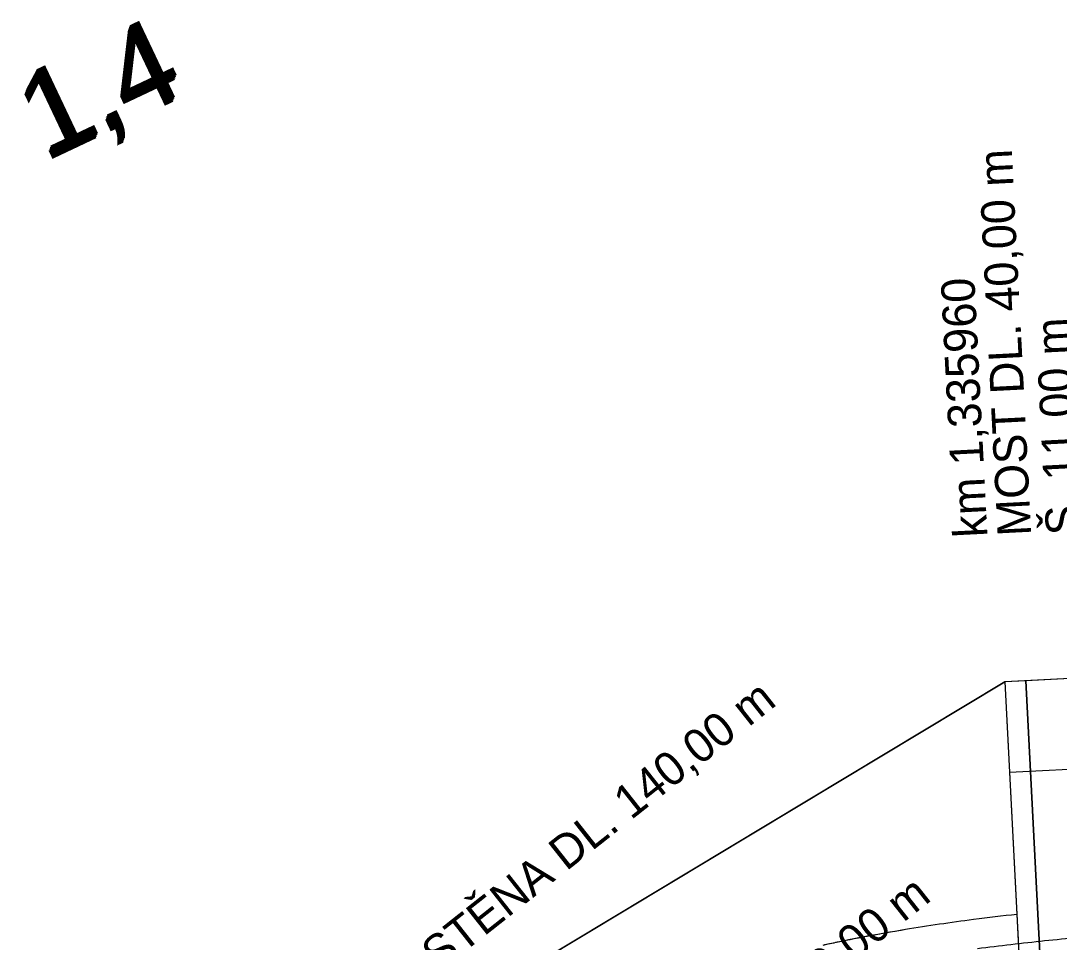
# Model space of a CAD drawing. Extents: x -606444 to -604546, y -1158114 to -1156869.
# Drawn here: x -606155.8 to -606032.4, y -1157301.1 to -1157191.5 of the extents above; entities that cross this region are included whole.
import ezdxf

# ---------------------------------------------------------------- set-up
doc = ezdxf.new("R2010")
doc.units = 0
for name, color, linetype in [('B_CHOD', 7, 'Continuous'), ('B_TRAM', 7, 'Continuous'), ('B_VOZ', 7, 'Continuous'), ('B_ZELEN', 7, 'Continuous'), ('NS_VB', 7, 'Continuous'), ('NS_VB_OBJ', 7, 'Continuous'), ('NS_VB_POP', 7, 'Continuous'), ('OSA', 7, 'Continuous'), ('OSAPOP', 7, 'Continuous')]:
    doc.layers.add(name, color=color, linetype=linetype)

msp = doc.modelspace()

# ---------------------------------------------------------------- linework, layer by layer
at = {"layer": 'B_CHOD'}
for p, q in [((-606036.36, -1157270), (-606038.86, -1157270.13)), ((-606038.86, -1157270.13), (-606035.78, -1157330.33)), ((-606033.28, -1157330.2), (-606036.36, -1157270))]:
    msp.add_line(p, q, dxfattribs=at)
msp.add_lwpolyline([(-606036.36, -1157270), (-606036.36, -1157270)], dxfattribs=at)
at = {"layer": 'B_TRAM'}
msp.add_lwpolyline([(-606037.44, -1157297.79), (-606036.88, -1157308.8)], dxfattribs=at)
for centre, radius, start, end in [((-606011.41, -1157540.2), 243.79, 97.3485, 99.2721), ((-605999.21, -1157634.73), 339.1, 96.473, 97.3485), ((-606019.94, -1157487.94), 190.83, 99.2721, 101.7459), ((-606024.29, -1157466.37), 168.83, 101.7883, 102.3854)]:
    msp.add_arc(centre, radius, start, end, dxfattribs=at)
at = {"layer": 'B_VOZ'}
for p, q in [((-606030.37, -1157269.7), (-606036.36, -1157270)), ((-606036.36, -1157270), (-606033.28, -1157330.2))]:
    msp.add_line(p, q, dxfattribs=at)
msp.add_lwpolyline([(-606036.36, -1157270), (-606036.36, -1157270)], dxfattribs=at)
at = {"layer": 'B_ZELEN'}
msp.add_lwpolyline([(-606113.95, -1157315.31), (-606038.86, -1157270.13), (-606037.44, -1157297.79)], dxfattribs=at)
for centre, radius, start, end in [((-606011.41, -1157540.2), 243.79, 97.3485, 99.2721), ((-605999.21, -1157634.73), 339.1, 96.473, 97.3485), ((-606020.21, -1157486.26), 189.13, 99.2721, 102.3012)]:
    msp.add_arc(centre, radius, start, end, dxfattribs=at)
at = {"layer": 'NS_VB'}
for p, q in [((-605965.95, -1157266.41), (-606038.86, -1157270.13)), ((-606038.86, -1157270.13), (-606113.95, -1157315.31)), ((-606038.86, -1157270.13), (-606035.78, -1157330.33)), ((-606036.36, -1157270), (-606033.28, -1157330.2))]:
    msp.add_line(p, q, dxfattribs=at)
for centre, radius, start, end in [((-606011.41, -1157540.2), 243.79, 97.3485, 99.2721), ((-605999.21, -1157634.73), 339.1, 96.473, 97.3485), ((-606019.94, -1157487.94), 190.83, 99.2721, 101.7459), ((-606024.29, -1157466.37), 168.83, 101.7883, 102.3854)]:
    msp.add_arc(centre, radius, start, end, dxfattribs=at)
at = {"layer": 'NS_VB_OBJ'}
msp.add_lwpolyline([(-606038.31, -1157280.88), (-606027.32, -1157280.32)], dxfattribs=at)
at = {"layer": 'OSA'}
for centre, radius, start, end in [((-605999.21, -1157634.73), 335.6, 95.9745, 97.3485), ((-605976.07, -1157855.92), 558, 95.1501, 95.9745)]:
    msp.add_arc(centre, radius, start, end, dxfattribs=at)

# ---------------------------------------------------------------- texts
at = {"layer": 'NS_VB_POP'}
for s, rotation, p in [('MOST DL. 40,00 m', 92.9074, (-606035.72, -1157252.72)), ('km 1,335960', 92.9074, (-606040.93, -1157252.87)), ('Š. 11,00 m', 92.9074, (-606029.95, -1157252.57)), ('NÍZKÁ PROTIHLUKOVÁ STĚNA DL. 140,00 m', 38.3478, (-606153.71, -1157342.32)), ('NÍZKÁ PROTIHLUKOVÁ STĚNA DL. 130,00 m', 38.3478, (-606135.32, -1157365.56))]:
    msp.add_text(s, height=4, rotation=rotation, dxfattribs=at).set_placement(p)
at = {"layer": 'OSAPOP'}
for p in [(-606153, -1157208.38), (-606152.93, -1157208.18), (-606152.86, -1157207.98), (-606152.79, -1157207.79)]:
    msp.add_text('1,4', height=10, rotation=25.3051, dxfattribs=at).set_placement(p)

doc.saveas('drawing.dxf')
